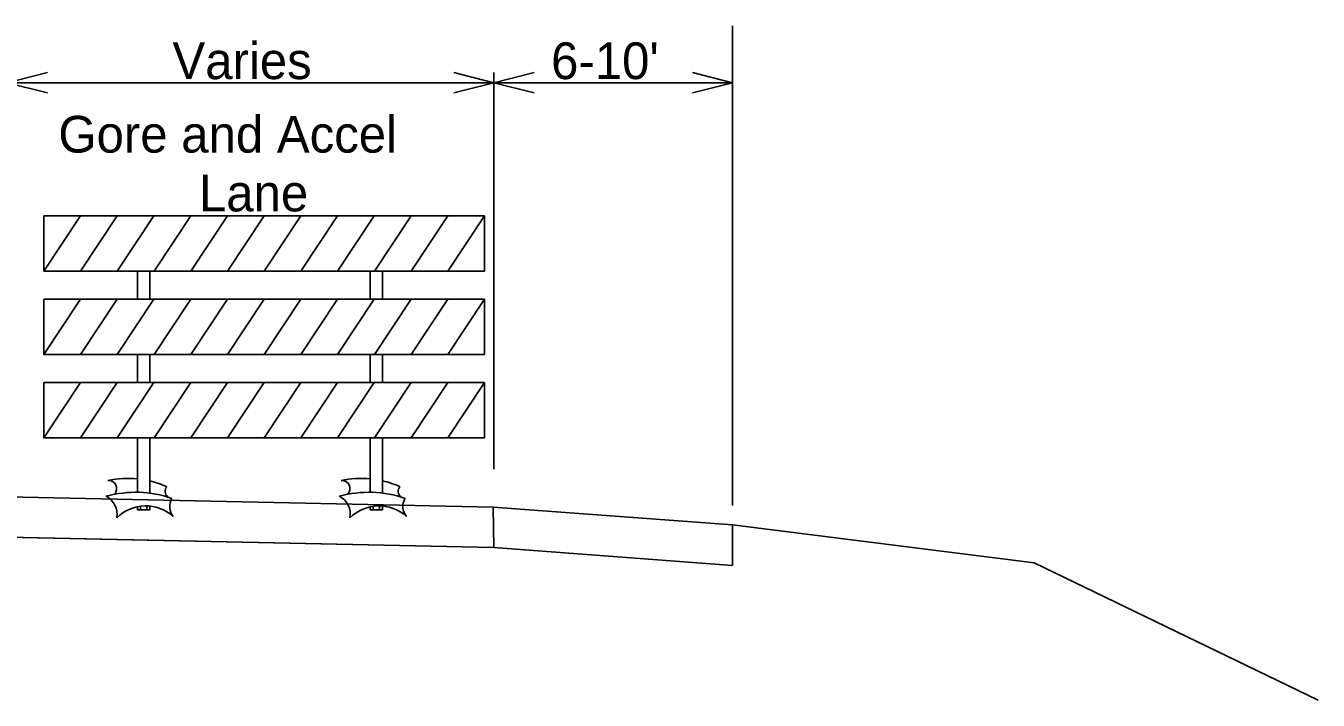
# Model space of a CAD drawing. Extents: x 10133 to 81668, y 4856 to 11018.
# Drawn here: x 12363 to 12891, y 4991 to 5267 of the extents above; entities that cross this region are included whole.
import ezdxf

# ---------------------------------------------------------------- set-up
doc = ezdxf.new("R2010")
doc.units = 0
for name, color, linetype in [('Cell', 7, 'Continuous'), ('dsnXsPCCPavementBottom', 7, 'Continuous'), ('dsnXsShldrEarthFill', 7, 'Continuous'), ('dsnXsShldrGranular', 7, 'Continuous'), ('dsnXsShldrGranularBottom', 7, 'Continuous'), ('dsnXsShldrSpecialBackBottom', 7, 'Continuous')]:
    doc.layers.add(name, color=color, linetype=linetype)

msp = doc.modelspace()

# ---------------------------------------------------------------- linework, layer by layer
at = {"layer": 'Cell'}
for p, q in [((12370.79, 5188.98), (12370.79, 5166.48)), ((12370.79, 5166.48), (12385.77, 5188.98)), ((12385.77, 5188.98), (12370.79, 5188.98)), ((12370.79, 5166.48), (12385.77, 5188.98)), ((12385.77, 5188.98), (12400.77, 5188.98)), ((12400.77, 5188.98), (12385.79, 5166.48)), ((12400.77, 5188.98), (12385.79, 5166.48)), ((12400.77, 5166.48), (12415.76, 5188.98)), ((12415.76, 5188.98), (12400.77, 5188.98)), ((12400.77, 5166.48), (12415.75, 5188.98)), ((12415.76, 5188.98), (12430.76, 5188.98)), ((12430.76, 5188.98), (12415.77, 5166.48)), ((12430.76, 5188.98), (12415.77, 5166.48)), ((12430.76, 5166.48), (12445.74, 5188.98)), ((12445.74, 5188.98), (12430.76, 5188.98)), ((12430.76, 5166.48), (12445.74, 5188.98)), ((12445.74, 5188.98), (12460.74, 5188.98)), ((12460.74, 5188.98), (12445.76, 5166.48)), ((12460.74, 5188.98), (12445.76, 5166.48)), ((12460.74, 5166.48), (12475.72, 5188.98)), ((12475.72, 5188.98), (12460.74, 5188.98)), ((12460.74, 5166.48), (12475.72, 5188.98)), ((12475.72, 5188.98), (12490.72, 5188.98)), ((12490.72, 5188.98), (12475.74, 5166.48)), ((12490.72, 5188.98), (12475.74, 5166.48)), ((12490.72, 5166.48), (12505.7, 5188.98)), ((12505.7, 5188.98), (12490.72, 5188.98)), ((12490.72, 5166.48), (12505.7, 5188.98)), ((12505.7, 5188.98), (12520.7, 5188.98)), ((12520.7, 5188.98), (12505.72, 5166.48)), ((12520.7, 5188.98), (12505.72, 5166.48)), ((12520.7, 5166.48), (12535.68, 5188.98)), ((12535.68, 5188.98), (12520.7, 5188.98)), ((12520.7, 5166.48), (12535.68, 5188.98)), ((12535.68, 5188.98), (12550.68, 5188.98)), ((12550.68, 5188.98), (12535.7, 5166.48)), ((12550.68, 5188.98), (12535.7, 5166.48)), ((12550.68, 5166.48), (12550.68, 5188.98)), ((12385.79, 5166.48), (12370.79, 5166.48)), ((12385.79, 5166.48), (12400.77, 5166.48)), ((12415.77, 5166.48), (12400.77, 5166.48)), ((12409.06, 5166.48), (12409.06, 5154.94)), ((12414.06, 5166.48), (12414.06, 5154.94)), ((12415.77, 5166.48), (12430.76, 5166.48)), ((12445.76, 5166.48), (12430.76, 5166.48)), ((12445.76, 5166.48), (12460.74, 5166.48)), ((12475.74, 5166.48), (12460.74, 5166.48)), ((12475.74, 5166.48), (12490.72, 5166.48)), ((12505.72, 5166.48), (12490.72, 5166.48)), ((12504.06, 5166.48), (12504.06, 5154.94)), ((12505.72, 5166.48), (12520.7, 5166.48)), ((12509.06, 5166.48), (12509.06, 5154.94)), ((12535.7, 5166.48), (12520.7, 5166.48)), ((12535.7, 5166.48), (12550.68, 5166.48)), ((12370.79, 5154.94), (12370.79, 5132.45)), ((12370.79, 5132.45), (12385.77, 5154.94)), ((12385.77, 5154.94), (12370.79, 5154.94)), ((12370.79, 5132.45), (12385.77, 5154.94)), ((12385.77, 5154.94), (12400.77, 5154.94)), ((12400.77, 5154.94), (12385.79, 5132.45)), ((12400.77, 5154.94), (12385.79, 5132.45)), ((12400.77, 5132.45), (12415.76, 5154.94)), ((12415.76, 5154.94), (12400.77, 5154.94)), ((12400.77, 5132.45), (12415.75, 5154.94)), ((12415.76, 5154.94), (12430.76, 5154.94)), ((12430.76, 5154.94), (12415.77, 5132.45)), ((12430.76, 5154.94), (12415.77, 5132.45)), ((12430.76, 5132.45), (12445.74, 5154.94)), ((12445.74, 5154.94), (12430.76, 5154.94)), ((12430.76, 5132.45), (12445.74, 5154.94)), ((12445.74, 5154.94), (12460.74, 5154.94)), ((12460.74, 5154.94), (12445.76, 5132.45)), ((12460.74, 5154.94), (12445.76, 5132.45)), ((12460.74, 5132.45), (12475.72, 5154.94)), ((12475.72, 5154.94), (12460.74, 5154.94)), ((12460.74, 5132.45), (12475.72, 5154.94)), ((12475.72, 5154.94), (12490.72, 5154.94)), ((12490.72, 5154.94), (12475.74, 5132.45)), ((12490.72, 5154.94), (12475.74, 5132.45)), ((12490.72, 5132.45), (12505.7, 5154.94)), ((12505.7, 5154.94), (12490.72, 5154.94)), ((12490.72, 5132.45), (12505.7, 5154.94)), ((12505.7, 5154.94), (12520.7, 5154.94)), ((12520.7, 5154.94), (12505.72, 5132.45)), ((12520.7, 5154.94), (12505.72, 5132.45)), ((12520.7, 5132.45), (12535.68, 5154.94)), ((12535.68, 5154.94), (12520.7, 5154.94)), ((12520.7, 5132.45), (12535.68, 5154.94)), ((12535.68, 5154.94), (12550.68, 5154.94)), ((12550.68, 5154.94), (12535.7, 5132.45)), ((12550.68, 5154.94), (12535.7, 5132.45)), ((12550.68, 5132.44), (12550.68, 5154.94)), ((12385.79, 5132.45), (12370.79, 5132.45)), ((12385.79, 5132.45), (12400.77, 5132.45)), ((12415.77, 5132.45), (12400.77, 5132.45)), ((12409.06, 5132.45), (12409.06, 5120.91)), ((12414.06, 5132.45), (12414.06, 5120.91)), ((12415.77, 5132.45), (12430.76, 5132.45)), ((12445.76, 5132.45), (12430.76, 5132.45)), ((12445.76, 5132.45), (12460.74, 5132.45)), ((12475.74, 5132.45), (12460.74, 5132.45)), ((12475.74, 5132.45), (12490.72, 5132.45)), ((12505.72, 5132.45), (12490.72, 5132.45)), ((12504.06, 5132.45), (12504.06, 5120.91)), ((12505.72, 5132.44), (12520.7, 5132.44)), ((12509.06, 5132.44), (12509.06, 5120.91)), ((12535.7, 5132.45), (12520.7, 5132.45)), ((12535.7, 5132.44), (12550.68, 5132.44)), ((12370.79, 5120.91), (12370.79, 5098.41)), ((12370.79, 5098.41), (12385.77, 5120.91)), ((12385.77, 5120.91), (12370.79, 5120.91)), ((12370.79, 5098.41), (12385.77, 5120.91)), ((12385.77, 5120.91), (12400.77, 5120.91)), ((12400.77, 5120.91), (12385.79, 5098.41)), ((12400.77, 5120.91), (12385.79, 5098.41)), ((12400.77, 5098.41), (12415.76, 5120.91)), ((12415.76, 5120.91), (12400.77, 5120.91)), ((12400.77, 5098.41), (12415.75, 5120.91)), ((12415.76, 5120.91), (12430.76, 5120.91)), ((12430.76, 5120.91), (12415.77, 5098.41)), ((12430.76, 5120.91), (12415.77, 5098.41)), ((12430.76, 5098.41), (12445.74, 5120.91)), ((12445.74, 5120.91), (12430.76, 5120.91)), ((12430.76, 5098.41), (12445.74, 5120.91)), ((12445.74, 5120.91), (12460.74, 5120.91)), ((12460.74, 5120.91), (12445.76, 5098.41)), ((12460.74, 5120.91), (12445.76, 5098.41)), ((12460.74, 5098.41), (12475.72, 5120.91)), ((12475.72, 5120.91), (12460.74, 5120.91)), ((12460.74, 5098.41), (12475.72, 5120.91)), ((12475.72, 5120.91), (12490.72, 5120.91)), ((12490.72, 5120.91), (12475.74, 5098.41)), ((12490.72, 5120.91), (12475.74, 5098.41)), ((12490.72, 5098.41), (12505.7, 5120.91)), ((12505.7, 5120.91), (12490.72, 5120.91)), ((12490.72, 5098.41), (12505.7, 5120.91)), ((12505.7, 5120.91), (12520.7, 5120.91)), ((12520.7, 5120.91), (12505.72, 5098.41)), ((12520.7, 5120.91), (12505.72, 5098.41)), ((12520.7, 5098.41), (12535.68, 5120.91)), ((12535.68, 5120.91), (12520.7, 5120.91)), ((12520.7, 5098.41), (12535.68, 5120.91)), ((12535.68, 5120.91), (12550.68, 5120.91)), ((12550.68, 5120.91), (12535.7, 5098.41)), ((12550.68, 5120.91), (12535.7, 5098.41)), ((12550.68, 5098.41), (12550.68, 5120.91)), ((12385.79, 5098.41), (12370.79, 5098.41)), ((12385.79, 5098.41), (12400.77, 5098.41)), ((12415.77, 5098.41), (12400.77, 5098.41)), ((12409.06, 5098.41), (12409.06, 5076.14)), ((12414.06, 5098.41), (12414.06, 5075.77)), ((12415.77, 5098.41), (12430.76, 5098.41)), ((12445.76, 5098.41), (12430.76, 5098.41)), ((12445.76, 5098.41), (12460.74, 5098.41)), ((12475.74, 5098.41), (12460.74, 5098.41)), ((12475.74, 5098.41), (12490.72, 5098.41)), ((12505.72, 5098.41), (12490.72, 5098.41)), ((12504.06, 5098.41), (12504.06, 5076.14)), ((12505.72, 5098.41), (12520.7, 5098.41)), ((12509.06, 5098.41), (12509.06, 5075.8)), ((12535.7, 5098.41), (12520.7, 5098.41)), ((12535.7, 5098.41), (12550.68, 5098.41)), ((12409.06, 5070.26), (12409.06, 5068.98)), ((12410.32, 5070.47), (12410.32, 5068.98)), ((12412.85, 5070.59), (12412.85, 5068.98)), ((12414.11, 5070.51), (12414.11, 5068.98)), ((12504, 5070.21), (12504, 5068.98)), ((12505.27, 5070.21), (12505.27, 5068.98)), ((12507.79, 5070.53), (12507.79, 5068.98)), ((12509.06, 5070.53), (12509.06, 5068.98)), ((12409.06, 5068.98), (12414.11, 5068.98)), ((12504, 5068.98), (12509.06, 5068.98))]:
    msp.add_line(p, q, dxfattribs=at)
for points in [[(12370.79, 5188.98), (12550.68, 5188.98), (12550.68, 5166.48), (12370.79, 5166.48)], [(12370.79, 5154.94), (12550.68, 5154.94), (12550.68, 5132.44), (12370.79, 5132.45)], [(12370.79, 5120.91), (12550.68, 5120.91), (12550.68, 5098.41), (12370.79, 5098.41)]]:
    msp.add_lwpolyline(points, close=True, dxfattribs=at)
for points in [[(12385.77, 5188.98), (12385.77, 5188.98)], [(12400.77, 5188.98), (12400.77, 5188.98)], [(12415.76, 5188.98), (12415.76, 5188.98)], [(12430.76, 5188.98), (12430.76, 5188.98)], [(12445.74, 5188.98), (12445.74, 5188.98)], [(12460.74, 5188.98), (12460.74, 5188.98)], [(12475.72, 5188.98), (12475.72, 5188.98)], [(12490.72, 5188.98), (12490.72, 5188.98)], [(12505.7, 5188.98), (12505.7, 5188.98)], [(12520.7, 5188.98), (12520.7, 5188.98)], [(12535.68, 5188.98), (12535.68, 5188.98)], [(12385.79, 5166.48), (12385.79, 5166.48)], [(12400.77, 5166.48), (12400.77, 5166.48)], [(12415.77, 5166.48), (12415.77, 5166.48)], [(12430.76, 5166.48), (12430.76, 5166.48)], [(12445.76, 5166.48), (12445.76, 5166.48)], [(12460.74, 5166.48), (12460.74, 5166.48)], [(12475.74, 5166.48), (12475.74, 5166.48)], [(12490.72, 5166.48), (12490.72, 5166.48)], [(12505.72, 5166.48), (12505.72, 5166.48)], [(12520.7, 5166.48), (12520.7, 5166.48)], [(12535.7, 5166.48), (12535.7, 5166.48)], [(12385.77, 5154.94), (12385.77, 5154.94)], [(12400.77, 5154.94), (12400.77, 5154.94)], [(12415.76, 5154.94), (12415.76, 5154.94)], [(12430.76, 5154.94), (12430.76, 5154.94)], [(12445.74, 5154.94), (12445.74, 5154.94)], [(12460.74, 5154.94), (12460.74, 5154.94)], [(12475.72, 5154.94), (12475.72, 5154.94)], [(12490.72, 5154.94), (12490.72, 5154.94)], [(12505.7, 5154.94), (12505.7, 5154.94)], [(12520.7, 5154.94), (12520.7, 5154.94)], [(12535.68, 5154.94), (12535.68, 5154.94)], [(12385.79, 5132.45), (12385.79, 5132.45)], [(12400.77, 5132.45), (12400.77, 5132.45)], [(12415.77, 5132.45), (12415.77, 5132.45)], [(12430.76, 5132.45), (12430.76, 5132.45)], [(12445.76, 5132.45), (12445.76, 5132.45)], [(12460.74, 5132.45), (12460.74, 5132.45)], [(12475.74, 5132.45), (12475.74, 5132.45)], [(12490.72, 5132.45), (12490.72, 5132.45)], [(12505.72, 5132.45), (12505.72, 5132.44)], [(12520.7, 5132.44), (12520.7, 5132.45)], [(12535.7, 5132.45), (12535.7, 5132.44)], [(12385.77, 5120.91), (12385.77, 5120.91)], [(12400.77, 5120.91), (12400.77, 5120.91)], [(12415.76, 5120.91), (12415.76, 5120.91)], [(12430.76, 5120.91), (12430.76, 5120.91)], [(12445.74, 5120.91), (12445.74, 5120.91)], [(12460.74, 5120.91), (12460.74, 5120.91)], [(12475.72, 5120.91), (12475.72, 5120.91)], [(12490.72, 5120.91), (12490.72, 5120.91)], [(12505.7, 5120.91), (12505.7, 5120.91)], [(12520.7, 5120.91), (12520.7, 5120.91)], [(12535.68, 5120.91), (12535.68, 5120.91)], [(12385.79, 5098.41), (12385.79, 5098.41)], [(12400.77, 5098.41), (12400.77, 5098.41)], [(12415.77, 5098.41), (12415.77, 5098.41)], [(12430.76, 5098.41), (12430.76, 5098.41)], [(12445.76, 5098.41), (12445.76, 5098.41)], [(12460.74, 5098.41), (12460.74, 5098.41)], [(12475.74, 5098.41), (12475.74, 5098.41)], [(12490.72, 5098.41), (12490.72, 5098.41)], [(12505.72, 5098.41), (12505.72, 5098.41)], [(12520.7, 5098.41), (12520.7, 5098.41)], [(12535.7, 5098.41), (12535.7, 5098.41)]]:
    msp.add_lwpolyline(points, dxfattribs=at)
for centre, major_axis, start_param, end_param in [((12405, 5042.2), (0, 39.63), 6.17953, 6.488027), ((12397.18, 5077.62), (0, -3.38), 0.855268, 3.201967), ((12399.77, 5023.49), (0, 59.04), 5.971972, 6.036694), ((12500.21, 5042.2), (0, 39.63), 6.186849, 6.488027), ((12492.39, 5077.62), (0, -3.38), 0.855268, 3.201967), ((12500.21, 5042.2), (0, 39.63), 5.864085, 6.056873), ((12408.21, 5030.11), (0, 46.03), 5.952082, 6.54644), ((12405, 5042.2), (0, 39.63), 5.864085, 5.953629), ((12422.93, 5076.51), (0, -2.68), 3.932498, 5.712469), ((12503.42, 5030.11), (0, 46.03), 5.952082, 6.54644), ((12518.15, 5076.51), (0, -2.68), 3.932498, 5.712469), ((12392.39, 5067.19), (0, 8.34), 4.530409, 5.814818), ((12412.37, 5053.79), (0, 16.81), 5.5448, 7.068002), ((12428.57, 5070.31), (0, 6.43), 1.025309, 2.259691), ((12487.6, 5067.19), (0, 8.34), 4.530409, 5.814818), ((12507.59, 5053.79), (0, 16.81), 5.5448, 7.068002), ((12523.78, 5070.31), (0, 6.43), 1.025309, 2.259691)]:
    msp.add_ellipse(centre, major_axis=major_axis, ratio=0.995, start_param=start_param, end_param=end_param, dxfattribs=at)
at = {"layer": 'dsnXsPCCPavementBottom'}
for p, q in [((12651.94, 5070.74), (12651.94, 5266.58)), ((12554.54, 5247.47), (12554.54, 5085.6)), ((12554.54, 5243.37), (12355.86, 5243.37)), ((12554.54, 5243.37), (12651.94, 5243.37))]:
    msp.add_line(p, q, dxfattribs=at)
for points in [[(12372.25, 5239.27), (12355.86, 5243.37), (12372.25, 5247.47)], [(12538.15, 5247.47), (12554.54, 5243.37), (12538.15, 5239.27)], [(12570.93, 5239.27), (12554.54, 5243.37), (12570.93, 5247.47)], [(12635.55, 5247.47), (12651.94, 5243.37), (12635.55, 5239.27)]]:
    msp.add_lwpolyline(points, dxfattribs=at)
at = {"layer": 'dsnXsShldrGranular'}
for points in [[(12355.86, 5074.33), (12554.3, 5070.11), (12554.54, 5053.55), (12356.1, 5057.76)], [(12651.94, 5062.84), (12554.3, 5070.11), (12554.54, 5053.55), (12651.94, 5046.24)]]:
    msp.add_lwpolyline(points, close=True, dxfattribs=at)
at = {"layer": 'dsnXsShldrGranularBottom'}
for p, q in [((12355.86, 5074.33), (12554.3, 5070.11)), ((12554.3, 5070.11), (12554.54, 5053.55)), ((12554.3, 5070.11), (12554.54, 5053.55)), ((12554.3, 5070.11), (12554.54, 5053.55)), ((12651.94, 5062.84), (12775.05, 5047.37)), ((12355.51, 5057.78), (12554.54, 5053.55)), ((12775.05, 5047.37), (12891.04, 4991.26))]:
    msp.add_line(p, q, dxfattribs=at)
at = {"layer": 'dsnXsShldrSpecialBackBottom'}
for p, q in [((12554.3, 5070.11), (12651.94, 5062.84)), ((12651.94, 5062.84), (12651.94, 5046.24)), ((12554.54, 5053.55), (12651.94, 5046.24))]:
    msp.add_line(p, q, dxfattribs=at)

# ---------------------------------------------------------------- texts
at = {"layer": 'dsnXsShldrEarthFill'}
for s, p in [('Varies', (12423.3, 5244.83)), ('Gore and Accel', (12376.72, 5214.83)), ('Lane', (12434.11, 5190.83))]:
    msp.add_text(s, height=15, dxfattribs=at).set_placement(p)
msp.add_text("6-10'", height=15, rotation=0, dxfattribs=at).set_placement((12577.88, 5244.83))

doc.saveas('drawing.dxf')
